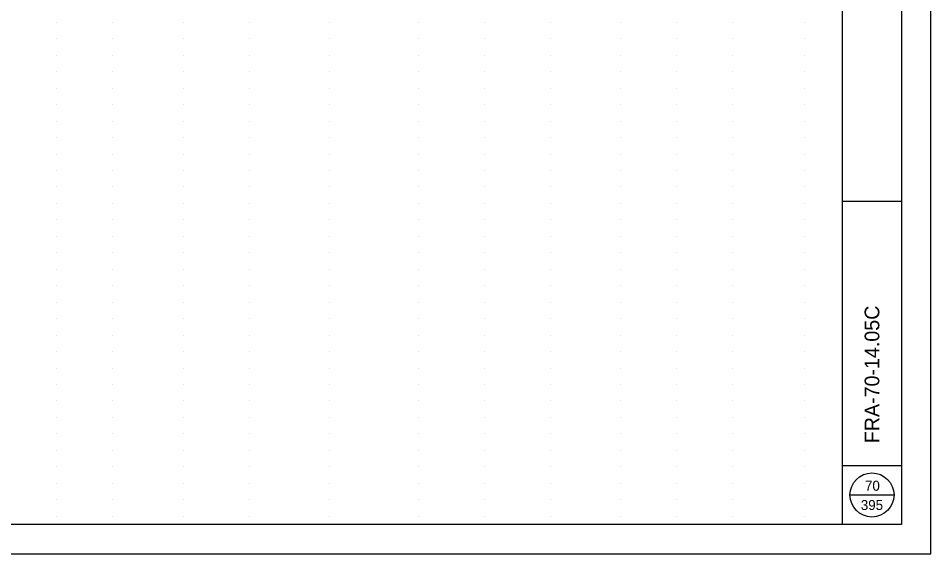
# Model space of a CAD drawing. Extents: x -15.4 to 18.6, y -12.6 to 9.4.
# Drawn here: x 3.11 to 18.64, y -12.61 to -3.5 of the extents above; entities that cross this region are included whole.
import ezdxf

# ---------------------------------------------------------------- set-up
doc = ezdxf.new("R2010")
doc.units = 0
for name, color, linetype in [('SH_Border', 7, 'Continuous'), ('SH_Cut_Line', 7, 'Continuous'), ('SH_Data', 7, 'Continuous')]:
    doc.layers.add(name, color=color, linetype=linetype)

msp = doc.modelspace()

# ---------------------------------------------------------------- linework, layer by layer
at = {"layer": 'SH_Border'}
for p, q in [((17.143, -12.112), (17.143, 8.888)), ((17.143, -6.612), (18.143, -6.612)), ((17.143, -11.112), (18.143, -11.112))]:
    msp.add_line(p, q, dxfattribs=at)
msp.add_lwpolyline([(-13.357, 8.888), (18.143, 8.888), (18.143, -12.112), (-13.357, -12.112)], close=True, dxfattribs=at)
at = {"layer": 'SH_Cut_Line'}
msp.add_lwpolyline([(-15.357, -12.612), (18.643, -12.612), (18.643, 9.388), (-15.357, 9.388)], close=True, dxfattribs=at)
at = {"layer": 'SH_Data'}
for p, q in [((3.768, -3.572), (3.768, -3.572)), ((4.718, -3.572), (4.718, -3.572)), ((5.918, -3.572), (5.918, -3.572)), ((7.043, -3.572), (7.043, -3.572)), ((8.418, -3.572), (8.418, -3.572)), ((9.918, -3.572), (9.918, -3.572)), ((11.043, -3.572), (11.043, -3.572)), ((12.168, -3.572), (12.168, -3.572)), ((13.368, -3.572), (13.368, -3.572)), ((14.318, -3.572), (14.318, -3.572)), ((15.268, -3.572), (15.268, -3.572)), ((16.493, -3.572), (16.493, -3.572)), ((3.768, -3.852), (3.768, -3.852)), ((4.718, -3.852), (4.718, -3.852)), ((5.918, -3.852), (5.918, -3.852)), ((7.043, -3.852), (7.043, -3.852)), ((8.418, -3.852), (8.418, -3.852)), ((9.918, -3.852), (9.918, -3.852)), ((11.043, -3.852), (11.043, -3.852)), ((12.168, -3.852), (12.168, -3.852)), ((13.368, -3.852), (13.368, -3.852)), ((14.318, -3.852), (14.318, -3.852)), ((15.268, -3.852), (15.268, -3.852)), ((16.493, -3.852), (16.493, -3.852)), ((3.768, -4.132), (3.768, -4.132)), ((4.718, -4.132), (4.718, -4.132)), ((5.918, -4.132), (5.918, -4.132)), ((7.043, -4.132), (7.043, -4.132)), ((8.418, -4.132), (8.418, -4.132)), ((9.918, -4.132), (9.918, -4.132)), ((11.043, -4.132), (11.043, -4.132)), ((12.168, -4.132), (12.168, -4.132)), ((13.368, -4.132), (13.368, -4.132)), ((14.318, -4.132), (14.318, -4.132)), ((15.268, -4.132), (15.268, -4.132)), ((16.493, -4.132), (16.493, -4.132)), ((3.768, -4.412), (3.768, -4.412)), ((4.718, -4.412), (4.718, -4.412)), ((5.918, -4.412), (5.918, -4.412)), ((7.043, -4.412), (7.043, -4.412)), ((8.418, -4.412), (8.418, -4.412)), ((9.918, -4.412), (9.918, -4.412)), ((11.043, -4.412), (11.043, -4.412)), ((12.168, -4.412), (12.168, -4.412)), ((13.368, -4.412), (13.368, -4.412)), ((14.318, -4.412), (14.318, -4.412)), ((15.268, -4.412), (15.268, -4.412)), ((16.493, -4.412), (16.493, -4.412)), ((3.768, -4.692), (3.768, -4.692)), ((4.718, -4.692), (4.718, -4.692)), ((5.918, -4.692), (5.918, -4.692)), ((7.043, -4.692), (7.043, -4.692)), ((8.418, -4.692), (8.418, -4.692)), ((9.918, -4.692), (9.918, -4.692)), ((11.043, -4.692), (11.043, -4.692)), ((12.168, -4.692), (12.168, -4.692)), ((13.368, -4.692), (13.368, -4.692)), ((14.318, -4.692), (14.318, -4.692)), ((15.268, -4.692), (15.268, -4.692)), ((16.493, -4.692), (16.493, -4.692)), ((3.768, -4.972), (3.768, -4.972)), ((4.718, -4.972), (4.718, -4.972)), ((5.918, -4.972), (5.918, -4.972)), ((7.043, -4.972), (7.043, -4.972)), ((8.418, -4.972), (8.418, -4.972)), ((9.918, -4.972), (9.918, -4.972)), ((11.043, -4.972), (11.043, -4.972)), ((12.168, -4.972), (12.168, -4.972)), ((13.368, -4.972), (13.368, -4.972)), ((14.318, -4.972), (14.318, -4.972)), ((15.268, -4.972), (15.268, -4.972)), ((16.493, -4.972), (16.493, -4.972)), ((3.768, -5.252), (3.768, -5.252)), ((4.718, -5.252), (4.718, -5.252)), ((5.918, -5.252), (5.918, -5.252)), ((7.043, -5.252), (7.043, -5.252)), ((8.418, -5.252), (8.418, -5.252)), ((9.918, -5.252), (9.918, -5.252)), ((11.043, -5.252), (11.043, -5.252)), ((12.168, -5.252), (12.168, -5.252)), ((13.368, -5.252), (13.368, -5.252)), ((14.318, -5.252), (14.318, -5.252)), ((15.268, -5.252), (15.268, -5.252)), ((16.493, -5.252), (16.493, -5.252)), ((3.768, -5.532), (3.768, -5.532)), ((4.718, -5.532), (4.718, -5.532)), ((5.918, -5.532), (5.918, -5.532)), ((7.043, -5.532), (7.043, -5.532)), ((8.418, -5.532), (8.418, -5.532)), ((9.918, -5.532), (9.918, -5.532)), ((11.043, -5.532), (11.043, -5.532)), ((12.168, -5.532), (12.168, -5.532)), ((13.368, -5.532), (13.368, -5.532)), ((14.318, -5.532), (14.318, -5.532)), ((15.268, -5.532), (15.268, -5.532)), ((16.493, -5.532), (16.493, -5.532)), ((3.768, -5.812), (3.768, -5.812)), ((4.718, -5.812), (4.718, -5.812)), ((5.918, -5.812), (5.918, -5.812)), ((7.043, -5.812), (7.043, -5.812)), ((8.418, -5.812), (8.418, -5.812)), ((9.918, -5.812), (9.918, -5.812)), ((11.043, -5.812), (11.043, -5.812)), ((12.168, -5.812), (12.168, -5.812)), ((13.368, -5.812), (13.368, -5.812)), ((14.318, -5.812), (14.318, -5.812)), ((15.268, -5.812), (15.268, -5.812)), ((16.493, -5.812), (16.493, -5.812)), ((3.768, -6.092), (3.768, -6.092)), ((4.718, -6.092), (4.718, -6.092)), ((5.918, -6.092), (5.918, -6.092)), ((7.043, -6.092), (7.043, -6.092)), ((8.418, -6.092), (8.418, -6.092)), ((9.918, -6.092), (9.918, -6.092)), ((11.043, -6.092), (11.043, -6.092)), ((12.168, -6.092), (12.168, -6.092)), ((13.368, -6.092), (13.368, -6.092)), ((14.318, -6.092), (14.318, -6.092)), ((15.268, -6.092), (15.268, -6.092)), ((16.493, -6.092), (16.493, -6.092)), ((3.768, -6.372), (3.768, -6.372)), ((4.718, -6.372), (4.718, -6.372)), ((5.918, -6.372), (5.918, -6.372)), ((7.043, -6.372), (7.043, -6.372)), ((8.418, -6.372), (8.418, -6.372)), ((9.918, -6.372), (9.918, -6.372)), ((11.043, -6.372), (11.043, -6.372)), ((12.168, -6.372), (12.168, -6.372)), ((13.368, -6.372), (13.368, -6.372)), ((14.318, -6.372), (14.318, -6.372)), ((15.268, -6.372), (15.268, -6.372)), ((16.493, -6.372), (16.493, -6.372)), ((3.768, -6.652), (3.768, -6.652)), ((4.718, -6.652), (4.718, -6.652)), ((5.918, -6.652), (5.918, -6.652)), ((7.043, -6.652), (7.043, -6.652)), ((8.418, -6.652), (8.418, -6.652)), ((9.918, -6.652), (9.918, -6.652)), ((11.043, -6.652), (11.043, -6.652)), ((12.168, -6.652), (12.168, -6.652)), ((13.368, -6.652), (13.368, -6.652)), ((14.318, -6.652), (14.318, -6.652)), ((15.268, -6.652), (15.268, -6.652)), ((16.493, -6.652), (16.493, -6.652)), ((3.768, -6.932), (3.768, -6.932)), ((4.718, -6.932), (4.718, -6.932)), ((5.918, -6.932), (5.918, -6.932)), ((7.043, -6.932), (7.043, -6.932)), ((8.418, -6.932), (8.418, -6.932)), ((9.918, -6.932), (9.918, -6.932)), ((11.043, -6.932), (11.043, -6.932)), ((12.168, -6.932), (12.168, -6.932)), ((13.368, -6.932), (13.368, -6.932)), ((14.318, -6.932), (14.318, -6.932)), ((15.268, -6.932), (15.268, -6.932)), ((16.493, -6.932), (16.493, -6.932)), ((3.768, -7.212), (3.768, -7.212)), ((4.718, -7.212), (4.718, -7.212)), ((5.918, -7.212), (5.918, -7.212)), ((7.043, -7.212), (7.043, -7.212)), ((8.418, -7.212), (8.418, -7.212)), ((9.918, -7.212), (9.918, -7.212)), ((11.043, -7.212), (11.043, -7.212)), ((12.168, -7.212), (12.168, -7.212)), ((13.368, -7.212), (13.368, -7.212)), ((14.318, -7.212), (14.318, -7.212)), ((15.268, -7.212), (15.268, -7.212)), ((16.493, -7.212), (16.493, -7.212)), ((3.768, -7.492), (3.768, -7.492)), ((4.718, -7.492), (4.718, -7.492)), ((5.918, -7.492), (5.918, -7.492)), ((7.043, -7.492), (7.043, -7.492)), ((8.418, -7.492), (8.418, -7.492)), ((9.918, -7.492), (9.918, -7.492)), ((11.043, -7.492), (11.043, -7.492)), ((12.168, -7.492), (12.168, -7.492)), ((13.368, -7.492), (13.368, -7.492)), ((14.318, -7.492), (14.318, -7.492)), ((15.268, -7.492), (15.268, -7.492)), ((16.493, -7.492), (16.493, -7.492)), ((3.768, -7.772), (3.768, -7.772)), ((4.718, -7.772), (4.718, -7.772)), ((5.918, -7.772), (5.918, -7.772)), ((7.043, -7.772), (7.043, -7.772)), ((8.418, -7.772), (8.418, -7.772)), ((9.918, -7.772), (9.918, -7.772)), ((11.043, -7.772), (11.043, -7.772)), ((12.168, -7.772), (12.168, -7.772)), ((13.368, -7.772), (13.368, -7.772)), ((14.318, -7.772), (14.318, -7.772)), ((15.268, -7.772), (15.268, -7.772)), ((16.493, -7.772), (16.493, -7.772)), ((3.768, -8.052), (3.768, -8.052)), ((4.718, -8.052), (4.718, -8.052)), ((5.918, -8.052), (5.918, -8.052)), ((7.043, -8.052), (7.043, -8.052)), ((8.418, -8.052), (8.418, -8.052)), ((9.918, -8.052), (9.918, -8.052)), ((11.043, -8.052), (11.043, -8.052)), ((12.168, -8.052), (12.168, -8.052)), ((13.368, -8.052), (13.368, -8.052)), ((14.318, -8.052), (14.318, -8.052)), ((15.268, -8.052), (15.268, -8.052)), ((16.493, -8.052), (16.493, -8.052)), ((3.768, -8.332), (3.768, -8.332)), ((4.718, -8.332), (4.718, -8.332)), ((5.918, -8.332), (5.918, -8.332)), ((7.043, -8.332), (7.043, -8.332)), ((8.418, -8.332), (8.418, -8.332)), ((9.918, -8.332), (9.918, -8.332)), ((11.043, -8.332), (11.043, -8.332)), ((12.168, -8.332), (12.168, -8.332)), ((13.368, -8.332), (13.368, -8.332)), ((14.318, -8.332), (14.318, -8.332)), ((15.268, -8.332), (15.268, -8.332)), ((16.493, -8.332), (16.493, -8.332)), ((3.768, -8.612), (3.768, -8.612)), ((4.718, -8.612), (4.718, -8.612)), ((5.918, -8.612), (5.918, -8.612)), ((7.043, -8.612), (7.043, -8.612)), ((8.418, -8.612), (8.418, -8.612)), ((9.918, -8.612), (9.918, -8.612)), ((11.043, -8.612), (11.043, -8.612)), ((12.168, -8.612), (12.168, -8.612)), ((13.368, -8.612), (13.368, -8.612)), ((14.318, -8.612), (14.318, -8.612)), ((15.268, -8.612), (15.268, -8.612)), ((16.493, -8.612), (16.493, -8.612)), ((3.768, -8.892), (3.768, -8.892)), ((4.718, -8.892), (4.718, -8.892)), ((5.918, -8.892), (5.918, -8.892)), ((7.043, -8.892), (7.043, -8.892)), ((8.418, -8.892), (8.418, -8.892)), ((9.918, -8.892), (9.918, -8.892)), ((11.043, -8.892), (11.043, -8.892)), ((12.168, -8.892), (12.168, -8.892)), ((13.368, -8.892), (13.368, -8.892)), ((14.318, -8.892), (14.318, -8.892)), ((15.268, -8.892), (15.268, -8.892)), ((16.493, -8.892), (16.493, -8.892)), ((3.768, -9.172), (3.768, -9.172)), ((4.718, -9.172), (4.718, -9.172)), ((5.918, -9.172), (5.918, -9.172)), ((7.043, -9.172), (7.043, -9.172)), ((8.418, -9.172), (8.418, -9.172)), ((9.918, -9.172), (9.918, -9.172)), ((11.043, -9.172), (11.043, -9.172)), ((12.168, -9.172), (12.168, -9.172)), ((13.368, -9.172), (13.368, -9.172)), ((14.318, -9.172), (14.318, -9.172)), ((15.268, -9.172), (15.268, -9.172)), ((16.493, -9.172), (16.493, -9.172)), ((3.768, -9.452), (3.768, -9.452)), ((4.718, -9.452), (4.718, -9.452)), ((5.918, -9.452), (5.918, -9.452)), ((7.043, -9.452), (7.043, -9.452)), ((8.418, -9.452), (8.418, -9.452)), ((9.918, -9.452), (9.918, -9.452)), ((11.043, -9.452), (11.043, -9.452)), ((12.168, -9.452), (12.168, -9.452)), ((13.368, -9.452), (13.368, -9.452)), ((14.318, -9.452), (14.318, -9.452)), ((15.268, -9.452), (15.268, -9.452)), ((16.493, -9.452), (16.493, -9.452)), ((3.768, -9.732), (3.768, -9.732)), ((4.718, -9.732), (4.718, -9.732)), ((5.918, -9.732), (5.918, -9.732)), ((7.043, -9.732), (7.043, -9.732)), ((8.418, -9.732), (8.418, -9.732)), ((9.918, -9.732), (9.918, -9.732)), ((11.043, -9.732), (11.043, -9.732)), ((12.168, -9.732), (12.168, -9.732)), ((13.368, -9.732), (13.368, -9.732)), ((14.318, -9.732), (14.318, -9.732)), ((15.268, -9.732), (15.268, -9.732)), ((16.493, -9.732), (16.493, -9.732)), ((3.768, -10.012), (3.768, -10.012)), ((4.718, -10.012), (4.718, -10.012)), ((5.918, -10.012), (5.918, -10.012)), ((7.043, -10.012), (7.043, -10.012)), ((8.418, -10.012), (8.418, -10.012)), ((9.918, -10.012), (9.918, -10.012)), ((11.043, -10.012), (11.043, -10.012)), ((12.168, -10.012), (12.168, -10.012)), ((13.368, -10.012), (13.368, -10.012)), ((14.318, -10.012), (14.318, -10.012)), ((15.268, -10.012), (15.268, -10.012)), ((16.493, -10.012), (16.493, -10.012)), ((3.768, -10.292), (3.768, -10.292)), ((4.718, -10.292), (4.718, -10.292)), ((5.918, -10.292), (5.918, -10.292)), ((7.043, -10.292), (7.043, -10.292)), ((8.418, -10.292), (8.418, -10.292)), ((9.918, -10.292), (9.918, -10.292)), ((11.043, -10.292), (11.043, -10.292)), ((12.168, -10.292), (12.168, -10.292)), ((13.368, -10.292), (13.368, -10.292)), ((14.318, -10.292), (14.318, -10.292)), ((15.268, -10.292), (15.268, -10.292)), ((16.493, -10.292), (16.493, -10.292)), ((3.768, -10.572), (3.768, -10.572)), ((4.718, -10.572), (4.718, -10.572)), ((5.918, -10.572), (5.918, -10.572)), ((7.043, -10.572), (7.043, -10.572)), ((8.418, -10.572), (8.418, -10.572)), ((9.918, -10.572), (9.918, -10.572)), ((11.043, -10.572), (11.043, -10.572)), ((12.168, -10.572), (12.168, -10.572)), ((13.368, -10.572), (13.368, -10.572)), ((14.318, -10.572), (14.318, -10.572)), ((15.268, -10.572), (15.268, -10.572)), ((16.493, -10.572), (16.493, -10.572)), ((3.768, -10.852), (3.768, -10.852)), ((4.718, -10.852), (4.718, -10.852)), ((5.918, -10.852), (5.918, -10.852)), ((7.043, -10.852), (7.043, -10.852)), ((8.418, -10.852), (8.418, -10.852)), ((9.918, -10.852), (9.918, -10.852)), ((11.043, -10.852), (11.043, -10.852)), ((12.168, -10.852), (12.168, -10.852)), ((13.368, -10.852), (13.368, -10.852)), ((14.318, -10.852), (14.318, -10.852)), ((15.268, -10.852), (15.268, -10.852)), ((16.493, -10.852), (16.493, -10.852)), ((3.768, -11.132), (3.768, -11.132)), ((4.718, -11.132), (4.718, -11.132)), ((5.918, -11.132), (5.918, -11.132)), ((7.043, -11.132), (7.043, -11.132)), ((8.418, -11.132), (8.418, -11.132)), ((9.918, -11.132), (9.918, -11.132)), ((11.043, -11.132), (11.043, -11.132)), ((12.168, -11.132), (12.168, -11.132)), ((13.368, -11.132), (13.368, -11.132)), ((14.318, -11.132), (14.318, -11.132)), ((15.268, -11.132), (15.268, -11.132)), ((16.493, -11.132), (16.493, -11.132)), ((3.768, -11.412), (3.768, -11.412)), ((4.718, -11.412), (4.718, -11.412)), ((5.918, -11.412), (5.918, -11.412)), ((7.043, -11.412), (7.043, -11.412)), ((8.418, -11.412), (8.418, -11.412)), ((9.918, -11.412), (9.918, -11.412)), ((11.043, -11.412), (11.043, -11.412)), ((12.168, -11.412), (12.168, -11.412)), ((13.368, -11.412), (13.368, -11.412)), ((14.318, -11.412), (14.318, -11.412)), ((15.268, -11.412), (15.268, -11.412)), ((16.493, -11.412), (16.493, -11.412)), ((17.268, -11.612), (18.018, -11.612)), ((3.768, -11.692), (3.768, -11.692)), ((4.718, -11.692), (4.718, -11.692)), ((5.918, -11.692), (5.918, -11.692)), ((7.043, -11.692), (7.043, -11.692)), ((8.418, -11.692), (8.418, -11.692)), ((9.918, -11.692), (9.918, -11.692)), ((11.043, -11.692), (11.043, -11.692)), ((12.168, -11.692), (12.168, -11.692)), ((13.368, -11.692), (13.368, -11.692)), ((14.318, -11.692), (14.318, -11.692)), ((15.268, -11.692), (15.268, -11.692)), ((16.493, -11.692), (16.493, -11.692)), ((3.768, -11.972), (3.768, -11.972)), ((4.718, -11.972), (4.718, -11.972)), ((5.918, -11.972), (5.918, -11.972)), ((7.043, -11.972), (7.043, -11.972)), ((8.418, -11.972), (8.418, -11.972)), ((9.918, -11.972), (9.918, -11.972)), ((11.043, -11.972), (11.043, -11.972)), ((12.168, -11.972), (12.168, -11.972)), ((13.368, -11.972), (13.368, -11.972)), ((14.318, -11.972), (14.318, -11.972)), ((15.268, -11.972), (15.268, -11.972)), ((16.493, -11.972), (16.493, -11.972))]:
    msp.add_line(p, q, dxfattribs=at)
msp.add_circle((17.643, -11.612), 0.375, dxfattribs=at)

# ---------------------------------------------------------------- texts
msp.add_text(' FRA-70-14.05C  ', height=0.25, rotation=90, dxfattribs=at).set_placement((17.768, -10.825))
for s, p in [('70', (17.524, -11.54)), ('395', (17.453, -11.868))]:
    msp.add_text(s, height=0.17, dxfattribs=at).set_placement(p)

doc.saveas('drawing.dxf')
